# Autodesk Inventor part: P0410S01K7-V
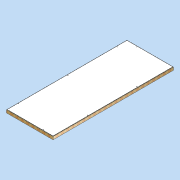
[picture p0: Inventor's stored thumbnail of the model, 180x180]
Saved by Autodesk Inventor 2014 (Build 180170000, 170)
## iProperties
Justset: False
Created: 2011-04
Part Number: P0410S01K7-V
Document SubType Name: Modeling
Designer: david.appleford
Density: 0.186249 g/cm^3
Description: 1w x 2.5w 01 Panel - 7 Locks
Mass: 51000 g
Surface Area: 75332.5 cm^2
Volume: 273826 cm^3
Cost Center: £160.00
Material: Generic
Appearance: Wood (Pine)
Title: 1w x 2.5w 01 Panel - 7 Locks
Author: david.appleford
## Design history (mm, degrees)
sketch "Sketch1"
  geometry: L1 (0, 0)-(1220, 0); L2 (1220, 0)-(1220, 3050); L3 (1220, 3050)-(0, 3050); L4 (0, 3050)-(0, 0); L5 (34, 3016)-(1186, 3016); L6 (1186, 3016)-(1186, 34); L7 (1186, 34)-(34, 34); L8 (34, 34)-(34, 3016)
  constraints: 16 end point, 4 parallel, 2 perpendicular, 1 horizontal, 3 other
  dimensions: "d0" = 1220 distance between parallel lines of L2 L4 (= w); "d1" = 3050 distance between parallel lines of L1 L3 (= 2.5 x w); "d2" = 34 distance between parallel lines of L5 L3 (= 0.5 x t)
extrude "Extrusion1" new body sketch "Sketch1" distance "d3" = 68 (= t); taper "d4" = 0 deg
sketch "Sketch2"
  geometry: L1 (1186, 3016)-(1186, 34) reference; L2 (34, 3016)-(1186, 3016) reference; L3 (34, 34)-(34, 3016) reference; L4 (1186, 34)-(34, 34) reference; L5 (1176, 3006)-(1176, 44); L6 (1176, 44)-(44, 44); L7 (44, 44)-(44, 3006); L8 (44, 3006)-(1176, 3006); 1 further point
  constraints: 8 end point, 3 other
  dimensions: "d5" = 10 distance between parallel lines of L8 L2
extrude "Extrusion2" join sketch "Sketch2" distance "d6" = 6 (= sw); taper "d7" = 0 deg
sketch "Sketch3"
  geometry: L1 (-44, 3006)-(-1176, 3006) reference; L2 (-1176, 3006)-(-1176, 44) reference; L3 (-44, 44)-(-44, 3006) reference; L4 (-1176, 44)-(-44, 44) reference; 1 further point
extrude "Extrusion3" join sketch "Sketch3" distance "d8" = 6 (= sw); taper "d9" = 0 deg
sketch "Sketch4"
  geometry: L1 (34, 3016)-(1186, 3016) reference; L2 (1186, 3016)-(1186, 34) reference; L3 (1186, 34)-(34, 34) reference; L4 (34, 34)-(34, 3016) reference; 8 further points
  constraints: 3 vertical alignment
  dimensions: "d10" = 28 distance from line of point (305, 2988) L1 (= k); "d12" = 28 distance from line of L3 point (915, 62) (= k); "d13" = 28 distance from line of point (62, 305) L4 (= k); "d14" = 305 horizontal distance of point (305, 2988) point (0, 0) (= 0.25 x w); "d15" = 610 horizontal distance of point (915, 62) point (305, 2988) (= 0.5 x w); "d16" = 305 vertical distance of point (62, 305) point (0, 0) (= 0.25 x w); "d17" = 1220 distance of point (62, 305) point (62, 1525) (= w); "d18" = 1220 distance of point (62, 2745) point (62, 1525) (= w); "d19" = 610 vertical distance of point (1158, 915) point (62, 305) (= 0.5 x w); "d20" = 1220 distance of point (1158, 915) point (1158, 2135) (= w)
hole "Hole1" sketch "Sketch4" at (305, 2988), (62, 2745), (62, 1525), (62, 305), (1158, 2135), (1158, 915), (915, 62) diameter "d22" = 12 (= hd); stored, may be unused: countersink angle "d26" = 90 deg, drill point angle "d28" = 118 deg; dims "d23" = 6, "d24" = 4, "d25" = 2, "d27" = 8
body "Solid1"
node "Projected Loop1"
other parameters: "w" = 1220 [user parameter; used in 9 equation terms], "t" = 68 [user parameter; used in 2 equation terms], "e" = 16 [user parameter], "sw" = 6 [user parameter; used in 2 equation terms], "sc" = 9 [user parameter], "sf" = 12 [user parameter], "k" = 28 [user parameter; used in 3 equation terms], "hd" = 12 [user parameter; used in 1 equation term]
